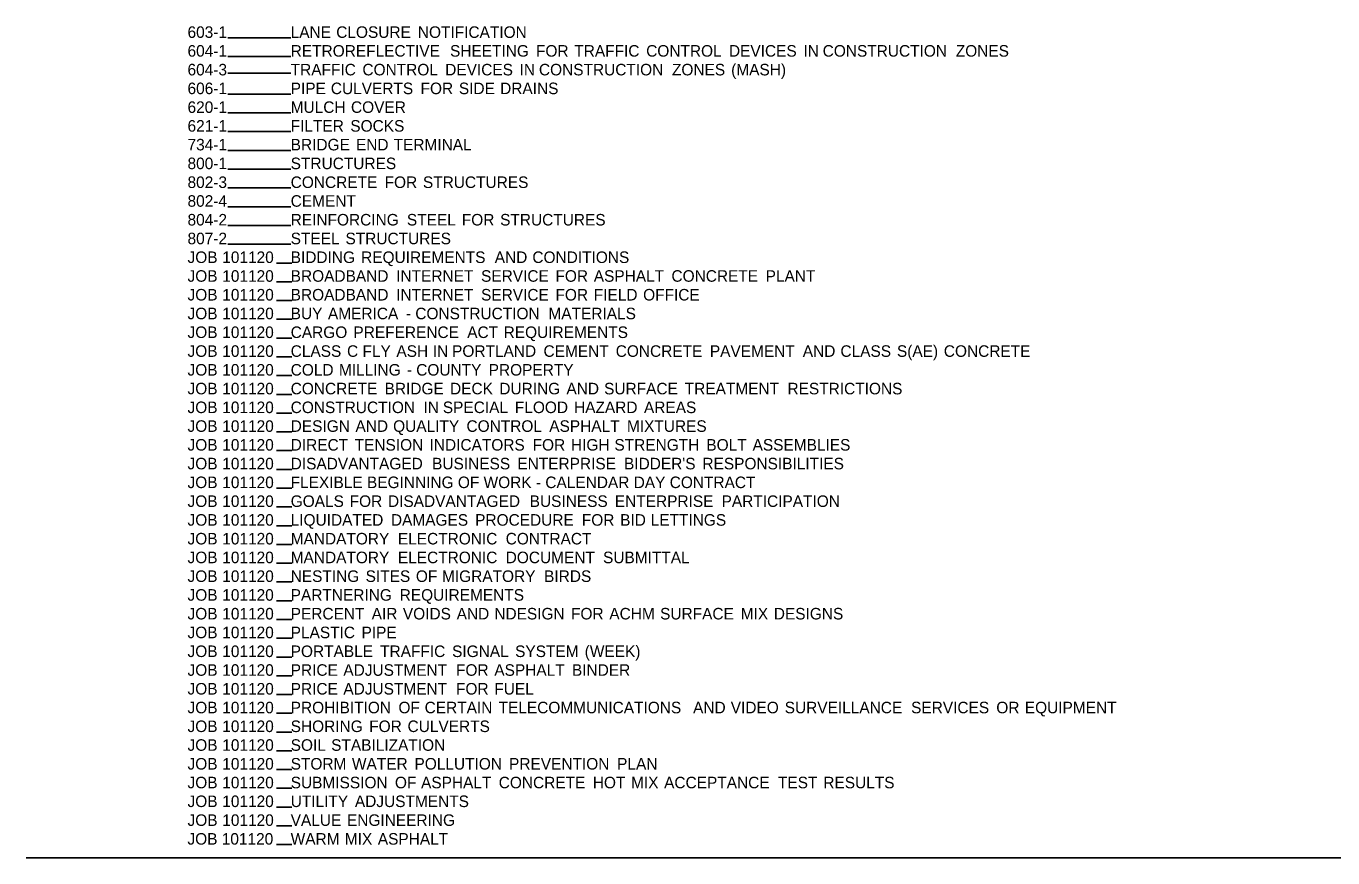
# Model space of a CAD drawing. Extents: x 1334737.6 to 1334769.5, y 402732.2 to 402752.6.
# Drawn here: x 1334737.56 to 1334753.53, y 402732.19 to 402742.34 of the extents above; entities that cross this region are included whole.
import ezdxf

# ---------------------------------------------------------------- set-up
doc = ezdxf.new("R2010")
doc.units = 0
doc.layers.add('Default', color=7, linetype='Continuous')
doc.layers.add('R_No Plot', color=7, linetype='Continuous')

msp = doc.modelspace()

# ---------------------------------------------------------------- linework, layer by layer
at = {"layer": 'Default'}
for p, q in [((1334740.029, 402742.2), (1334740.796, 402742.2)), ((1334740.029, 402741.971), (1334740.796, 402741.971)), ((1334740.029, 402741.771), (1334740.796, 402741.771)), ((1334740.029, 402741.513), (1334740.796, 402741.513)), ((1334740.029, 402741.284), (1334740.796, 402741.284)), ((1334740.029, 402741.055), (1334740.796, 402741.055)), ((1334740.029, 402740.826), (1334740.796, 402740.826)), ((1334740.029, 402740.597), (1334740.796, 402740.597)), ((1334740.029, 402740.367), (1334740.796, 402740.367)), ((1334740.029, 402740.138), (1334740.796, 402740.138)), ((1334740.029, 402739.909), (1334740.796, 402739.909)), ((1334740.029, 402739.68), (1334740.796, 402739.68)), ((1334740.621, 402739.451), (1334740.808, 402739.451)), ((1334740.621, 402739.222), (1334740.808, 402739.222)), ((1334740.621, 402738.993), (1334740.808, 402738.993)), ((1334740.621, 402738.764), (1334740.808, 402738.764)), ((1334740.621, 402738.535), (1334740.808, 402738.535)), ((1334740.621, 402738.305), (1334740.808, 402738.305)), ((1334740.621, 402738.076), (1334740.808, 402738.076)), ((1334740.621, 402737.847), (1334740.808, 402737.847)), ((1334740.621, 402737.618), (1334740.808, 402737.618)), ((1334740.621, 402737.389), (1334740.808, 402737.389)), ((1334740.621, 402737.16), (1334740.808, 402737.16)), ((1334740.621, 402736.931), (1334740.808, 402736.931)), ((1334740.621, 402736.702), (1334740.808, 402736.702)), ((1334740.621, 402736.472), (1334740.808, 402736.472)), ((1334740.621, 402736.243), (1334740.808, 402736.243)), ((1334740.621, 402736.014), (1334740.808, 402736.014)), ((1334740.621, 402735.785), (1334740.808, 402735.785)), ((1334740.621, 402735.556), (1334740.808, 402735.556)), ((1334740.621, 402735.327), (1334740.808, 402735.327)), ((1334740.621, 402735.098), (1334740.808, 402735.098)), ((1334740.621, 402734.869), (1334740.808, 402734.869)), ((1334740.621, 402734.639), (1334740.808, 402734.639)), ((1334740.621, 402734.41), (1334740.808, 402734.41)), ((1334740.621, 402734.181), (1334740.808, 402734.181)), ((1334740.621, 402733.952), (1334740.808, 402733.952)), ((1334740.621, 402733.723), (1334740.808, 402733.723)), ((1334740.621, 402733.494), (1334740.808, 402733.494)), ((1334740.621, 402733.265), (1334740.808, 402733.265)), ((1334740.621, 402733.036), (1334740.808, 402733.036)), ((1334740.621, 402732.807), (1334740.808, 402732.807)), ((1334740.621, 402732.577), (1334740.808, 402732.577)), ((1334740.621, 402732.348), (1334740.808, 402732.348))]:
    msp.add_line(p, q, dxfattribs=at)
at = {"layer": 'R_No Plot'}
msp.add_line((1334769.182, 402732.187), (1334737.564, 402732.187), dxfattribs=at)

# ---------------------------------------------------------------- texts
at = {"layer": 'Default'}
for s, p in [('603-1', (1334739.536, 402742.2)), ('LANE', (1334740.796, 402742.2)), (' CLOSURE', (1334741.3, 402742.2)), (' NOTIFICATION', (1334742.297, 402742.2)), ('604-1', (1334739.536, 402741.971)), ('RETROREFLECTIVE', (1334740.796, 402741.971)), (' SHEETING', (1334742.69, 402741.971)), (' FOR', (1334743.74, 402741.971)), (' TRAFFIC', (1334744.208, 402741.971)), (' CONTROL', (1334745.086, 402741.971)), (' DEVICES', (1334746.097, 402741.971)), (' IN', (1334747.007, 402741.971)), (' CONSTRUCTION', (1334747.242, 402741.971)), (' ZONES', (1334748.868, 402741.971)), ('604-3', (1334739.536, 402741.742)), ('TRAFFIC', (1334740.796, 402741.742)), (' CONTROL', (1334741.62, 402741.742)), (' DEVICES', (1334742.631, 402741.742)), (' IN', (1334743.54, 402741.742)), (' CONSTRUCTION', (1334743.776, 402741.742)), (' ZONES', (1334745.401, 402741.742)), (' (MASH)', (1334746.124, 402741.742)), ('606-1', (1334739.536, 402741.513)), ('PIPE', (1334740.796, 402741.513)), (' CULVERTS', (1334741.234, 402741.513)), (' FOR', (1334742.33, 402741.513)), (' SIDE', (1334742.798, 402741.513)), (' DRAINS', (1334743.302, 402741.513)), ('620-1', (1334739.536, 402741.284)), ('MULCH', (1334740.796, 402741.284)), (' COVER', (1334741.48, 402741.284)), ('621-1', (1334739.536, 402741.055)), ('FILTER', (1334740.796, 402741.055)), (' SOCKS', (1334741.472, 402741.055)), ('734-1', (1334739.536, 402740.826)), ('BRIDGE', (1334740.796, 402740.826)), (' END', (1334741.541, 402740.826)), (' TERMINAL', (1334742.001, 402740.826)), ('800-1', (1334739.536, 402740.597)), ('STRUCTURES', (1334740.796, 402740.597)), ('802-3', (1334739.536, 402740.367)), ('CONCRETE', (1334740.796, 402740.367)), (' FOR', (1334741.891, 402740.367)), (' STRUCTURES', (1334742.359, 402740.367)), ('802-4', (1334739.536, 402740.138)), ('CEMENT', (1334740.796, 402740.138)), ('804-2', (1334739.536, 402739.909)), ('REINFORCING', (1334740.796, 402739.909)), (' STEEL', (1334742.163, 402739.909)), (' FOR', (1334742.834, 402739.909)), (' STRUCTURES', (1334743.302, 402739.909)), ('807-2', (1334739.536, 402739.68)), ('STEEL', (1334740.796, 402739.68)), (' STRUCTURES', (1334741.413, 402739.68)), ('JOB', (1334739.536, 402739.451)), (' 101120', (1334739.908, 402739.451)), ('BIDDING', (1334740.796, 402739.451)), (' REQUIREMENTS', (1334741.604, 402739.451)), (' AND', (1334743.236, 402739.451)), (' CONDITIONS', (1334743.696, 402739.451)), ('JOB', (1334739.536, 402739.222)), (' 101120', (1334739.908, 402739.222)), ('BROADBAND', (1334740.796, 402739.222)), (' INTERNET', (1334742.033, 402739.222)), (' SERVICE', (1334743.069, 402739.222)), (' FOR', (1334743.978, 402739.222)), (' ASPHALT', (1334744.446, 402739.222)), (' CONCRETE', (1334745.395, 402739.222)), (' PLANT', (1334746.545, 402739.222)), ('JOB', (1334739.536, 402738.993)), (' 101120', (1334739.908, 402738.993)), ('BROADBAND', (1334740.796, 402738.993)), (' INTERNET', (1334742.033, 402738.993)), (' SERVICE', (1334743.069, 402738.993)), (' FOR', (1334743.978, 402738.993)), (' FIELD', (1334744.446, 402738.993)), (' OFFICE', (1334745.049, 402738.993)), ('JOB', (1334739.536, 402738.764)), (' 101120', (1334739.908, 402738.764)), ('BUY', (1334740.796, 402738.764)), (' AMERICA', (1334741.199, 402738.764)), (' CONSTRUCTION', (1334742.266, 402738.764)), (' MATERIALS', (1334743.892, 402738.764)), (' -', (1334742.152, 402738.764)), ('JOB', (1334739.536, 402738.535)), (' 101120', (1334739.908, 402738.535)), ('CARGO', (1334740.796, 402738.535)), (' PREFERENCE', (1334741.51, 402738.535)), (' ACT', (1334742.9, 402738.535)), (' REQUIREMENTS', (1334743.345, 402738.535)), ('JOB', (1334739.536, 402738.305)), (' 101120', (1334739.908, 402738.305)), ('CLASS', (1334740.796, 402738.305)), (' C', (1334741.432, 402738.305)), (' FLY', (1334741.621, 402738.305)), (' ASH', (1334742.035, 402738.305)), (' IN', (1334742.479, 402738.305)), (' PORTLAND', (1334742.715, 402738.305)), (' CEMENT', (1334743.832, 402738.305)), (' CONCRETE', (1334744.714, 402738.305)), (' PAVEMENT', (1334745.864, 402738.305)), (' AND', (1334746.999, 402738.305)), (' CLASS', (1334747.459, 402738.305)), (' S(AE)', (1334748.149, 402738.305)), (' CONCRETE', (1334748.722, 402738.305)), ('JOB', (1334739.536, 402738.076)), (' 101120', (1334739.908, 402738.076)), ('COLD', (1334740.796, 402738.076)), (' MILLING', (1334741.333, 402738.076)), (' -', (1334742.163, 402738.076)), (' COUNTY', (1334742.277, 402738.076)), (' PROPERTY', (1334743.162, 402738.076)), ('JOB', (1334739.536, 402737.847)), (' 101120', (1334739.908, 402737.847)), ('CONCRETE', (1334740.796, 402737.847)), (' BRIDGE', (1334741.891, 402737.847)), (' DECK', (1334742.69, 402737.847)), (' DURING', (1334743.292, 402737.847)), (' AND', (1334744.112, 402737.847)), (' SURFACE', (1334744.572, 402737.847)), (' TREATMENT', (1334745.557, 402737.847)), (' RESTRICTIONS', (1334746.812, 402737.847)), ('JOB', (1334739.536, 402737.618)), (' 101120', (1334739.908, 402737.618)), ('CONSTRUCTION', (1334740.796, 402737.618)), (' IN', (1334742.367, 402737.618)), (' SPECIAL', (1334742.602, 402737.618)), (' FLOOD', (1334743.482, 402737.618)), (' HAZARD', (1334744.205, 402737.618)), (' AREAS', (1334745.059, 402737.618)), ('JOB', (1334739.536, 402737.389)), (' 101120', (1334739.908, 402737.389)), ('DESIGN', (1334740.796, 402737.389)), (' AND', (1334741.535, 402737.389)), (' QUALITY', (1334741.995, 402737.389)), (' CONTROL', (1334742.891, 402737.389)), (' ASPHALT', (1334743.902, 402737.389)), (' MIXTURES', (1334744.851, 402737.389)), ('JOB', (1334739.536, 402737.16)), (' 101120', (1334739.908, 402737.16)), ('DIRECT', (1334740.796, 402737.16)), (' TENSION', (1334741.525, 402737.16)), (' INDICATORS', (1334742.44, 402737.16)), (' FOR', (1334743.699, 402737.16)), (' HIGH', (1334744.167, 402737.16)), (' STRENGTH', (1334744.698, 402737.16)), (' BOLT', (1334745.821, 402737.16)), (' ASSEMBLIES', (1334746.386, 402737.16)), ('JOB', (1334739.536, 402736.931)), (' 101120', (1334739.908, 402736.931)), ('DISADVANTAGED', (1334740.796, 402736.931)), (' BUSINESS', (1334742.471, 402736.931)), (' ENTERPRISE', (1334743.512, 402736.931)), (" BIDDER'S", (1334744.815, 402736.931)), (' RESPONSIBILITIES', (1334745.773, 402736.931)), ('JOB', (1334739.536, 402736.702)), (' 101120', (1334739.908, 402736.702)), ('FLEXIBLE BEGINNING OF WORK - CALENDAR DAY CONTRACT', (1334740.795, 402736.702)), ('JOB', (1334739.536, 402736.472)), (' 101120', (1334739.908, 402736.472)), ('GOALS', (1334740.796, 402736.472)), (' FOR', (1334741.464, 402736.472)), (' DISADVANTAGED', (1334741.932, 402736.472)), (' BUSINESS', (1334743.663, 402736.472)), (' ENTERPRISE', (1334744.703, 402736.472)), (' PARTICIPATION', (1334746.007, 402736.472)), ('JOB', (1334739.536, 402736.243)), (' 101120', (1334739.908, 402736.243)), ('LIQUIDATED', (1334740.796, 402736.243)), (' DAMAGES', (1334741.968, 402736.243)), (' PROCEDURE', (1334742.997, 402736.243)), (' FOR', (1334744.3, 402736.243)), (' BID', (1334744.768, 402736.243)), (' LETTINGS', (1334745.141, 402736.243)), ('JOB', (1334739.536, 402736.014)), (' 101120', (1334739.908, 402736.014)), ('MANDATORY', (1334740.796, 402736.014)), (' ELECTRONIC', (1334742.053, 402736.014)), (' CONTRACT', (1334743.37, 402736.014)), ('JOB', (1334739.536, 402735.785)), (' 101120', (1334739.908, 402735.785)), ('MANDATORY', (1334740.796, 402735.785)), (' ELECTRONIC', (1334742.053, 402735.785)), (' DOCUMENT', (1334743.37, 402735.785)), (' SUBMITTAL', (1334744.559, 402735.785)), ('JOB', (1334739.536, 402735.556)), (' 101120', (1334739.908, 402735.556)), ('NESTING', (1334740.796, 402735.556)), (' SITES', (1334741.659, 402735.556)), (' OF', (1334742.273, 402735.556)), (' MIGRATORY', (1334742.592, 402735.556)), (' BIRDS', (1334743.839, 402735.556)), ('JOB', (1334739.536, 402735.327)), (' 101120', (1334739.908, 402735.327)), ('PARTNERING', (1334740.796, 402735.327)), (' REQUIREMENTS', (1334742.075, 402735.327)), ('JOB', (1334739.536, 402735.098)), (' 101120', (1334739.908, 402735.098)), ('PERCENT', (1334740.796, 402735.098)), (' AIR', (1334741.733, 402735.098)), (' VOIDS', (1334742.114, 402735.098)), (' AND', (1334742.771, 402735.098)), (' NDESIGN', (1334743.231, 402735.098)), (' FOR', (1334744.168, 402735.098)), (' ACHM', (1334744.636, 402735.098)), (' SURFACE', (1334745.256, 402735.098)), (' MIX', (1334746.241, 402735.098)), (' DESIGNS', (1334746.645, 402735.098)), ('JOB', (1334739.536, 402734.869)), (' 101120', (1334739.908, 402734.869)), ('PLASTIC', (1334740.796, 402734.869)), (' PIPE', (1334741.609, 402734.869)), ('JOB', (1334739.536, 402734.639)), (' 101120', (1334739.908, 402734.639)), ('PORTABLE', (1334740.796, 402734.639)), (' TRAFFIC', (1334741.836, 402734.639)), (' SIGNAL', (1334742.715, 402734.639)), (' SYSTEM', (1334743.485, 402734.639)), (' (WEEK)', (1334744.335, 402734.639)), ('JOB', (1334739.536, 402734.41)), (' 101120', (1334739.908, 402734.41)), ('PRICE', (1334740.796, 402734.41)), (' ADJUSTMENT', (1334741.387, 402734.41)), (' FOR', (1334742.763, 402734.41)), (' ASPHALT', (1334743.231, 402734.41)), (' BINDER', (1334744.179, 402734.41)), ('JOB', (1334739.536, 402734.181)), (' 101120', (1334739.908, 402734.181)), ('PRICE', (1334740.796, 402734.181)), (' ADJUSTMENT', (1334741.387, 402734.181)), (' FOR', (1334742.763, 402734.181)), (' FUEL', (1334743.231, 402734.181)), ('JOB', (1334739.536, 402733.952)), (' 101120', (1334739.908, 402733.952)), ('PROHIBITION', (1334740.796, 402733.952)), (' OF', (1334742.06, 402733.952)), (' CERTAIN', (1334742.38, 402733.952)), (' TELECOMMUNICATIONS', (1334743.283, 402733.952)), (' AND', (1334745.659, 402733.952)), (' VIDEO', (1334746.119, 402733.952)), (' SURVEILLANCE', (1334746.778, 402733.952)), (' SERVICES', (1334748.322, 402733.952)), (' OR', (1334749.363, 402733.952)), (' EQUIPMENT', (1334749.711, 402733.952)), ('JOB', (1334739.536, 402733.723)), (' 101120', (1334739.908, 402733.723)), ('SHORING', (1334740.796, 402733.723)), (' FOR', (1334741.703, 402733.723)), (' CULVERTS', (1334742.171, 402733.723)), ('JOB', (1334739.536, 402733.494)), (' 101120', (1334739.908, 402733.494)), ('SOIL', (1334740.796, 402733.494)), (' STABILIZATION', (1334741.238, 402733.494)), ('JOB', (1334739.536, 402733.265)), (' 101120', (1334739.908, 402733.265)), ('STORM', (1334740.796, 402733.265)), (' WATER', (1334741.492, 402733.265)), (' POLLUTION', (1334742.256, 402733.265)), (' PREVENTION', (1334743.411, 402733.265)), (' PLAN', (1334744.731, 402733.265)), ('JOB', (1334739.536, 402733.036)), (' 101120', (1334739.908, 402733.036)), ('SUBMISSION', (1334740.796, 402733.036)), (' OF', (1334742.017, 402733.036)), (' ASPHALT', (1334742.336, 402733.036)), (' CONCRETE', (1334743.285, 402733.036)), (' HOT', (1334744.434, 402733.036)), (' MIX', (1334744.901, 402733.036)), (' ACCEPTANCE', (1334745.305, 402733.036)), (' TEST', (1334746.696, 402733.036)), (' RESULTS', (1334747.25, 402733.036)), ('JOB', (1334739.536, 402732.807)), (' 101120', (1334739.908, 402732.807)), ('UTILITY', (1334740.796, 402732.807)), (' ADJUSTMENTS', (1334741.528, 402732.807)), ('JOB', (1334739.536, 402732.577)), (' 101120', (1334739.908, 402732.577)), ('VALUE', (1334740.796, 402732.577)), (' ENGINEERING', (1334741.431, 402732.577)), ('JOB 101120', (1334739.535, 402732.348)), ('WARM', (1334740.796, 402732.348)), (' MIX', (1334741.405, 402732.348)), (' ASPHALT', (1334741.808, 402732.348))]:
    msp.add_text(s, height=0.141, dxfattribs=at).set_placement(p)

doc.saveas('drawing.dxf')
